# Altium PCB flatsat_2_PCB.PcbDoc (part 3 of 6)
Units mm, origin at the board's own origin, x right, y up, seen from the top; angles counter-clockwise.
Board outline 400 x 250 mm, 4 copper layers (Top Layer, FlatSat GND, FlatSat VCC, Bottom Layer), stack 2.102 mm thick; 196 components, 289 nets, 1724 pads, 1139 vias.
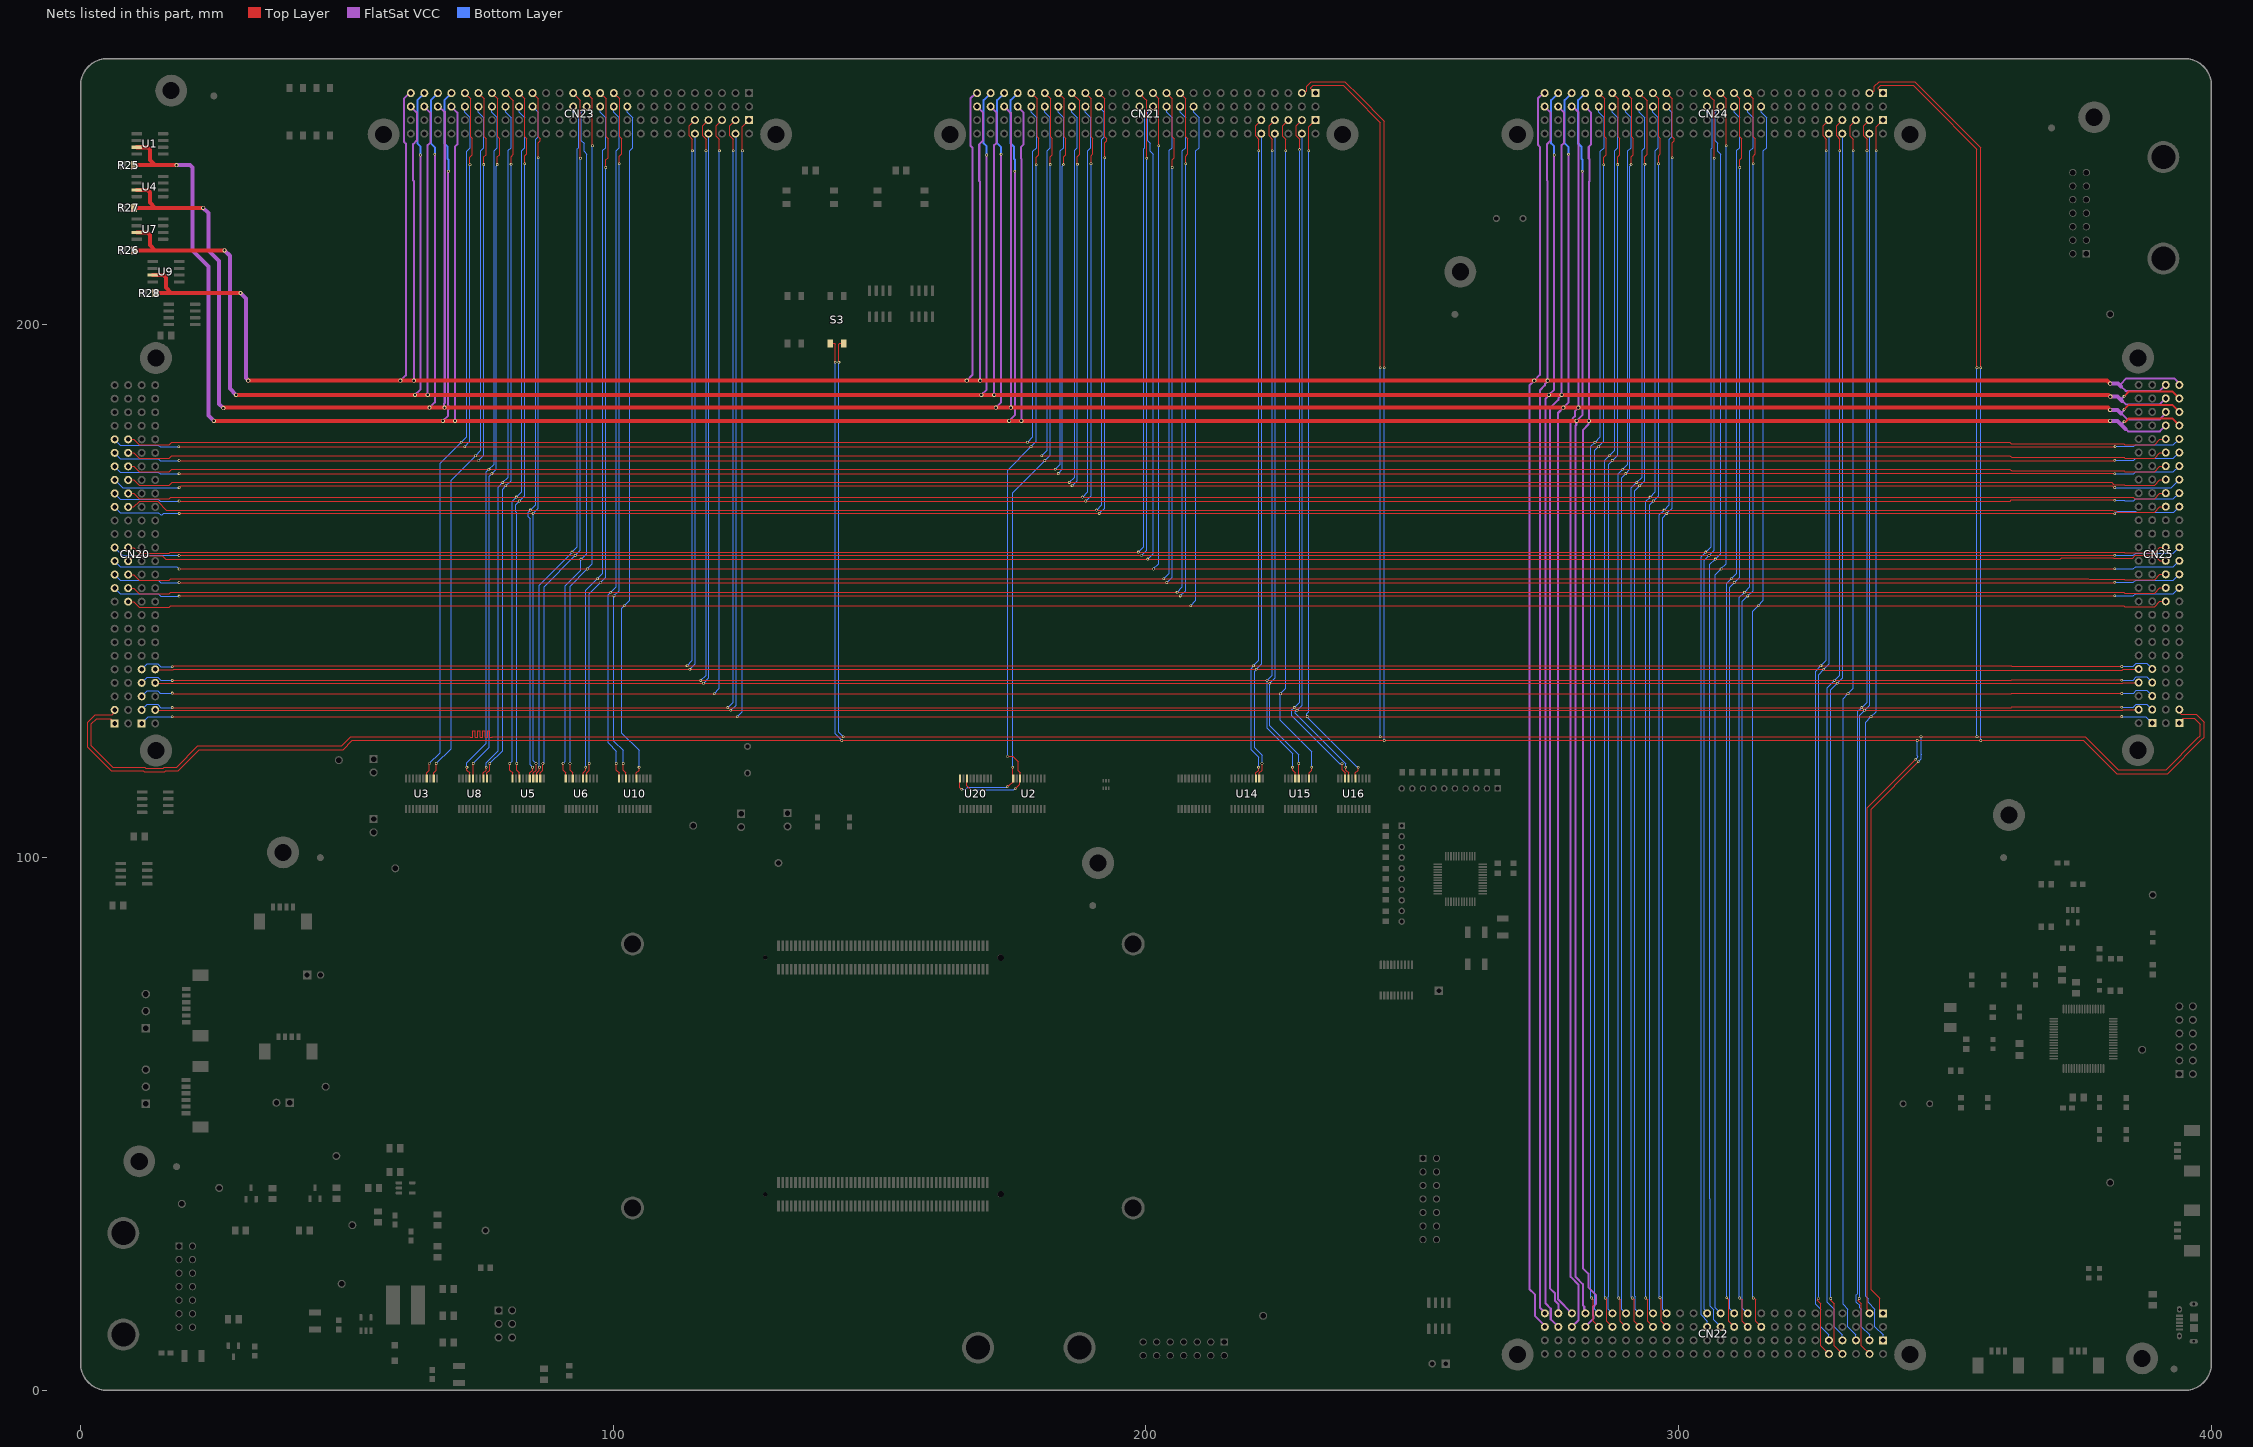
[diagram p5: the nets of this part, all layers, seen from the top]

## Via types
v1: diameter 0.508, hole 0.3, Top Layer to Bottom Layer, tented both sides, 1073 vias
v2: diameter 0.762, hole 0.45, Top Layer to Bottom Layer, tented both sides, 66 vias

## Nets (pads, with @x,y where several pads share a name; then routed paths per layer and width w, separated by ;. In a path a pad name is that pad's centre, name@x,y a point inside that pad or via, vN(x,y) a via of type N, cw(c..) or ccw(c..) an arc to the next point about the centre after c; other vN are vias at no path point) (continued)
H1-20: CN20.20 CN21.20 CN22.20 CN23.20 CN24.20 CN25.20 U10.15 | length 838.6
  Top Layer w0.203: CN20.20@8.92,148.06 10.004,148.06 11.034,147.03 16.604,147.03 16.88,147.307 v1(102.058,147.307) v1(208.378,147.307) v1(314.918,147.307) 383.54,147.307 383.762,147.085 389.332,147.085 390.361,148.115 CN25.20@391.445,148.115 ; U10.15@104.325,114.87 104.325,115.913 104.832,116.421 v1(104.832,116.994) ; v1(313.991,17.333) 314.145,17.333 314.479,16.999 314.479,13.945 314.48,13.944 314.48,13 315.508,11.972 CN22.20@315.508,11.923
  Bottom Layer w0.203: CN23.20@102.62,241 102.62,239.916 103.65,238.886 103.65,233.316 103.058,232.725 103.058,148.307 v1(102.058,147.307) 101.597,146.847 101.597,123.403 104.832,120.168 v1(104.832,116.994) ; v1(208.378,147.307) 209.378,148.307 209.378,232.725 209.97,233.316 209.97,238.886 208.94,239.916 CN21.20@208.94,241 ; v1(313.991,17.333) 313.932,17.391 313.932,17.59 313.918,17.605 313.918,36 313.918,146.307 v1(314.918,147.307) 315.918,148.307 315.918,232.725 316.51,233.316 316.51,238.886 315.48,239.916 CN24.20@315.48,241
H1-21: CN20.21 CN21.21 CN22.21 CN23.21 CN24.21 CN25.21 U10.18 | length 846.4
  Top Layer w0.203: v1(18.478,149.113) 18.505,149.14 v1(100.119,149.14) v1(206.439,149.14) v1(312.979,149.14) 381.861,149.14 v1(381.887,149.166) ; CN23.21@100.08,243.54 101.17,242.45 101.17,235.319 101.562,234.928 101.562,232.163 101.119,231.72 v1(101.119,230.295) ; v1(101.868,117.679) 101.868,116.421 102.375,115.913 U10.18@102.375,114.87 ; CN21.21@206.4,243.54 207.49,242.45 207.49,235.319 207.882,234.928 207.882,232.163 207.439,231.72 v1(207.439,230.295) ; CN24.21@312.94,243.54 314.03,242.45 314.03,235.319 314.422,234.928 314.422,232.163 313.979,231.72 v1(313.979,230.295)
  Bottom Layer w0.203: CN20.21@6.38,150.6 7.47,149.51 14.601,149.51 14.992,149.118 18.473,149.118 v1(18.478,149.113) ; v1(101.119,230.295) 101.119,150.14 v1(100.119,149.14) 100.119,121.881 101.868,120.132 v1(101.868,117.679) ; v1(206.439,149.14) 207.439,150.14 v1(207.439,230.295) ; CN22.21@312.968,14.463 311.979,15.452 311.979,36 311.979,148.14 v1(312.979,149.14) 313.979,150.14 v1(313.979,230.295) ; v1(381.887,149.166) 385.365,149.166 385.765,149.565 392.895,149.565 CN25.21@393.985,150.655
H1-22: CN20.22 CN21.22 CN22.22 CN23.22 CN24.22 CN25.22 U10.20 | length 835.4
  Top Layer w0.203: CN20.22@8.92,150.6 10.004,150.6 11.034,149.57 16.604,149.57 16.88,149.847 v1(99.517,149.847) v1(205.837,149.847) v1(312.377,149.847) 383.54,149.847 383.762,149.625 389.332,149.625 390.361,150.655 CN25.22@391.445,150.655 ; v1(100.568,117.679) 100.568,116.421 101.075,115.913 U10.20@101.075,114.87 ; v1(311.446,17.333) 311.605,17.333 311.939,16.999 311.939,13.945 311.94,13.944 311.94,13 312.968,11.972 CN22.22@312.968,11.923
  Bottom Layer w0.203: CN23.22@100.08,241 100.08,239.916 101.11,238.886 101.11,233.316 100.517,232.724 100.517,150.847 v1(99.517,149.847) 99,149.33 99,121.529 100.568,119.962 v1(100.568,117.679) ; v1(205.837,149.847) 206.837,150.847 206.837,232.724 207.43,233.316 207.43,238.886 206.4,239.916 CN21.22@206.4,241 ; v1(311.446,17.333) 311.387,17.391 311.387,17.594 311.377,17.605 311.377,36 311.377,148.847 v1(312.377,149.847) 313.377,150.847 313.377,232.724 313.97,233.316 313.97,238.886 312.94,239.916 CN24.22@312.94,241
H1-23: CN20.23 CN21.23 CN22.23 CN23.23 CN24.23 CN25.23 U6.14 | length 843.9
  Top Layer w0.203: v1(18.478,151.653) v1(97.584,151.653) v1(203.904,151.653) v1(310.444,151.653) 381.832,151.653 v1(381.887,151.708) ; U6.14@94.975,114.87 94.975,115.913 95.482,116.421 v1(95.482,117.679) ; CN23.23@97.54,243.54 98.63,242.45 98.63,235.319 99.027,234.923 99.027,231.442 98.584,230.999 v1(98.584,229.574) ; CN21.23@203.86,243.54 204.95,242.45 204.95,235.319 205.347,234.923 205.347,231.442 204.904,230.999 v1(204.904,229.574) ; CN24.23@310.4,243.54 311.49,242.45 311.49,235.319 311.887,234.923 311.887,231.442 311.444,230.999 v1(311.444,229.574)
  Bottom Layer w0.203: CN20.23@6.38,153.14 7.47,152.05 14.601,152.05 14.997,151.653 v1(18.478,151.653) ; v1(95.482,117.679) 95.482,149.552 v1(97.584,151.653) 98.584,152.653 v1(98.584,229.574) ; v1(203.904,151.653) 204.904,152.653 v1(204.904,229.574) ; CN22.23@310.428,14.463 309.575,15.317 309.575,150.784 v1(310.444,151.653) 311.444,152.653 v1(311.444,229.574) ; v1(381.887,151.708) 385.368,151.708 385.765,152.105 392.895,152.105 CN25.23@393.985,153.195
H1-24: CN20.24 CN21.24 CN22.24 CN23.24 CN24.24 CN25.24 U6.15 | length 832.6
  Top Layer w0.203: CN20.24@8.92,153.14 10.004,153.14 11.034,152.11 16.604,152.11 16.88,152.387 v1(97.018,152.387) v1(203.338,152.387) v1(309.878,152.387) 377,152.387 377.145,152.242 383.685,152.242 383.762,152.165 389.332,152.165 390.361,153.195 CN25.24@391.445,153.195 ; U6.15@94.325,114.87 94.325,115.913 94.832,116.421 v1(94.832,116.994) ; v1(309.041,17.37) 309.041,17.357 309.399,16.999 309.399,13.945 309.4,13.944 309.4,13 310.428,11.972 CN22.24@310.428,11.923
  Bottom Layer w0.203: v1(94.832,116.994) 94.832,150.201 v1(97.018,152.387) 98.018,153.387 98.018,232.765 98.57,233.316 98.57,238.886 97.54,239.916 CN23.24@97.54,241 ; v1(203.338,152.387) 204.338,153.387 204.338,232.765 204.89,233.316 204.89,238.886 203.86,239.916 CN21.24@203.86,241 ; v1(309.041,17.37) 309.041,151.55 310.878,153.387 310.878,232.765 311.43,233.316 311.43,238.886 310.4,239.916 CN24.24@310.4,241
H1-25: CN20.25 CN21.25 CN22.25 CN23.25 CN24.25 CN25.25 U6.18 | length 841
  Top Layer w0.203: v1(18.478,154.193) v1(95.086,154.193) v1(201.406,154.193) 307.946,154.193 381.832,154.193 v1(381.887,154.248) ; v1(91.868,117.679) 91.868,116.421 92.375,115.913 U6.18@92.375,114.87 ; CN23.25@95,243.54 96.086,242.454 v1(96.086,233.675) ; CN21.25@201.32,243.54 202.406,242.454 v1(202.406,233.675) ; CN24.25@307.86,243.54 308.946,242.454 v1(308.946,233.675) ; v1(307.96,154.184) v1@307.96,154.193
  Bottom Layer w0.203: CN20.25@6.38,155.68 7.466,154.594 18.078,154.594 v1(18.478,154.193) ; v1(91.868,117.679) 91.868,150.975 v1(95.086,154.193) 96.086,155.193 v1(96.086,233.675) ; v1(201.406,154.193) 202.406,155.193 v1(202.406,233.675) ; CN22.25@307.888,14.463 306.855,15.496 306.855,153.103 307.864,154.112 307.888,154.112 v1(307.96,154.184) ; v1@307.946,154.193 308.946,155.193 v1(308.946,233.675) ; v1(381.887,154.248) 385.368,154.248 385.765,154.645 392.895,154.645 CN25.25@393.985,155.735
H1-26: CN20.26 CN21.26 CN22.26 CN23.26 CN24.26 CN25.26 U6.20 | length 830.8
  Top Layer w0.203: CN20.26@8.92,155.68 9.95,156.71 15.29,156.71 15.94,156.06 94.007,156.06 200.336,156.06 v1(306.876,156.06) 371.626,156.06 371.884,156.318 381.602,156.318 381.666,156.255 385.244,156.255 385.754,156.764 389.332,156.764 390.361,155.735 CN25.26@391.445,155.735 ; v1(90.568,117.679) 90.568,116.421 91.075,115.913 U6.20@91.075,114.87
  Bottom Layer w0.203: v1(90.568,117.679) 91,118.111 91,151.039 92.183,152.222 93.922,153.961 v1(93.922,156.06) ; v1@94.007,156.06 94.016,156.06 95.016,157.06 95.016,232.075 94.504,232.587 94.504,234.096 93.97,234.63 93.97,239.97 CN23.26@95,241 ; v1(200.327,156.06) 200.336,156.06 201.336,157.06 201.336,232.075 200.824,232.587 200.824,234.096 200.29,234.63 200.29,239.97 CN21.26@201.32,241 ; CN24.26@307.86,241 306.83,239.97 306.83,234.63 307.364,234.096 307.364,232.587 307.876,232.075 307.876,157.06 v1(306.876,156.06) 305.876,155.06 305.876,36 305.888,35.987 305.888,15.799 306.571,15.117 306.571,13.241 CN22.26@307.888,11.923
H1-27: CN20.27 CN21.27 CN22.27 CN23.27 CN24.27 CN25.27 U5.12 | length 839.7
  Top Layer w0.203: v1(18.478,156.733) v1(92.836,156.733) v1(199.156,156.733) v1(305.696,156.733) 381.832,156.733 v1(381.887,156.788) ; U5.12@86.275,114.87 86.275,115.913 86.782,116.421 v1(86.782,117.679) ; CN23.27@92.46,243.54 93.49,242.51 93.836,242.164 v1(93.836,231.331) ; CN21.27@198.78,243.54 199.81,242.51 200.156,242.164 v1(200.156,231.331) ; CN24.27@305.32,243.54 306.35,242.51 306.696,242.164 v1(306.696,231.331)
  Bottom Layer w0.203: CN20.27@6.38,158.22 7.41,157.19 7.867,156.733 v1(18.478,156.733) ; v1(86.782,117.679) 86.782,117.733 87,117.95 87,150.898 v1(92.836,156.733) 93.836,157.733 v1(93.836,231.331) ; v1(199.156,156.733) 200.156,157.733 v1(200.156,231.331) ; CN22.27@305.348,14.463 305.348,14.709 304.821,15.236 304.821,35.995 304.826,36 304.826,155.864 v1(305.696,156.733) 306.696,157.733 v1(306.696,231.331) ; v1(381.887,156.788) 385.368,156.788 385.765,157.185 392.895,157.185 CN25.27@393.985,158.275
H1-28: CN20.28 CN21.28 CN22.28 CN23.28 CN24.28 CN25.28 U5.13 | length 828.8
  Top Layer w0.203: CN20.28@8.92,158.22 10.004,158.22 11.034,157.19 16.604,157.19 16.78,157.367 v1(92.235,157.367) v1(198.555,157.367) v1(305.095,157.367) 383.64,157.367 383.762,157.245 389.332,157.245 390.361,158.275 CN25.28@391.445,158.275 ; U5.13@85.625,114.87 85.625,115.913 86.132,116.421 v1(86.132,116.994)
  Bottom Layer w0.203: v1(86.132,116.994) 86.132,151.132 92.109,157.109 92.109,157.158 92.235,157.284 v1(92.235,157.367) 93.235,158.367 93.235,233.062 93.49,233.316 93.49,238.886 92.46,239.916 CN23.28@92.46,241 ; v1(198.555,157.367) 199.555,158.367 199.555,233.062 199.81,233.316 199.81,238.886 198.78,239.916 CN21.28@198.78,241 ; CN24.28@305.32,241 305.32,239.916 306.35,238.886 306.35,233.316 306.095,233.062 306.095,158.367 v1(305.095,157.367) 304.21,156.481 304.21,36 304.21,14.146 305.348,13.007 CN22.28@305.348,11.923
H1-33: CN20.33 CN21.33 CN22.33 CN23.33 CN24.33 CN25.33 U5.14 | length 830.4
  Top Layer w0.203: v1(18.5,164.623) v1(84.93,164.623) v1(191.25,164.623) v1(297.79,164.623) 381.779,164.623 v1(381.851,164.551) ; CN23.33@84.84,243.54 85.93,242.45 85.93,235.319 86.327,234.923 86.327,234.57 85.93,234.173 v1(85.93,231.42) ; U5.14@84.975,114.87 84.975,115.913 85.482,116.421 v1(85.482,117.679) ; CN21.33@191.16,243.54 192.25,242.45 192.25,235.319 192.647,234.923 192.647,234.57 192.25,234.173 v1(192.25,231.42) ; CN24.33@297.7,243.54 298.79,242.45 298.79,235.319 299.187,234.923 299.187,234.57 298.79,234.173 v1(298.79,231.42)
  Bottom Layer w0.203: CN20.33@6.38,165.84 7.47,164.75 14.601,164.75 14.997,164.353 15.35,164.353 15.619,164.623 v1(18.5,164.623) ; v1(85.482,117.679) 84.92,118.241 84.92,164.613 v1(84.93,164.623) 85.93,165.622 v1(85.93,231.42) ; v1(191.25,164.623) 192.25,165.622 v1(192.25,231.42) ; CN22.33@297.728,14.463 297.728,14.55 297.026,15.252 297.026,163.859 v1(297.79,164.623) 298.789,165.622 v1(298.79,231.42) ; v1(381.851,164.551) 382.339,165.04 385.764,165.04 385.939,164.865 392.956,164.865 CN25.33@393.985,165.895
H1-34: CN20.34 CN21.34 CN22.34 CN23.34 CN24.34 CN25.34 U5.15 | length 820
  Top Layer w0.203: CN20.34@8.92,165.84 10.004,165.84 11.054,166.89 14.435,166.89 16.068,165.257 v1(84.396,165.257) v1(190.716,165.257) v1(297.256,165.257) 381.532,165.257 381.704,165.085 382.072,165.085 382.291,164.865 389.332,164.865 390.361,165.895 CN25.34@391.445,165.895 ; U5.15@84.325,114.87 84.325,115.913 84.832,116.421 v1(84.832,116.994) ; v1(296.492,17.356) 296.492,17.206 296.699,16.999 296.699,13.945 296.7,13.944 296.7,13 297.728,11.972 CN22.34@297.728,11.923
  Bottom Layer w0.203: v1(84.832,116.994) 84.387,117.44 84.387,163.613 84,164 84,164.861 v1(84.396,165.257) 85.396,166.257 85.396,234.913 85.87,235.386 85.87,239.97 CN23.34@84.84,241 ; v1(190.716,165.257) 191.716,166.257 191.716,234.903 192.19,235.377 192.19,239.97 CN21.34@191.16,241 ; v1(296.492,17.356) 296.464,17.356 296.345,17.475 296.345,36 296.345,164.346 v1(297.256,165.257) 298.256,166.257 298.256,234.887 298.73,235.361 298.73,239.97 CN24.34@297.7,241
H1-35: CN20.35 CN21.35 CN22.35 CN23.35 CN24.35 CN25.35 U5.18 | length 827.9
  Top Layer w0.203: v1(18.478,166.954) v1(82.36,166.954) v1(188.68,166.954) v1(295.22,166.954) 362.236,166.954 362.434,167.152 381.839,167.152 v1(381.887,167.104) ; v1(81.868,117.679) 81.868,116.421 82.375,115.913 U5.18@82.375,114.87 ; CN23.35@82.3,243.54 83.39,242.45 83.39,235.319 83.726,234.983 83.726,232.157 83.36,231.79 v1(83.36,230.277) ; CN21.35@188.62,243.54 189.71,242.45 189.71,235.319 190.046,234.983 190.046,232.157 189.68,231.79 v1(189.68,230.277) ; CN24.35@295.16,243.54 296.25,242.45 296.25,235.319 296.586,234.983 296.586,232.157 296.22,231.79 v1(296.22,230.277)
  Bottom Layer w0.203: CN20.35@6.38,168.38 7.47,167.29 14.601,167.29 14.937,166.954 v1(18.478,166.954) ; v1(81.868,117.679) 81.868,164.694 81.646,164.915 81.646,166.24 v1(82.36,166.954) 83.36,167.954 v1(83.36,230.277) ; v1(188.68,166.954) 189.68,167.954 v1(189.68,230.277) ; CN22.35@295.188,14.463 295.188,14.468 294.529,15.127 294.529,166.263 v1(295.22,166.954) 296.22,167.954 v1(296.22,230.277) ; v1(381.887,167.104) 383.651,167.104 383.746,167.009 385.428,167.009 385.765,167.345 392.895,167.345 CN25.35@393.985,168.435
H1-36: CN20.36 CN21.36 CN22.36 CN23.36 CN24.36 CN25.36 U5.20 | length 817
  Top Layer w0.203: CN20.36@8.92,168.38 10.004,168.38 11.034,167.35 16.604,167.35 16.95,167.697 v1(81.768,167.697) v1(188.088,167.697) v1(294.628,167.697) 385.294,167.697 385.586,167.405 389.332,167.405 390.361,168.435 CN25.36@391.445,168.435 ; v1(80.568,117.679) 80.568,116.421 81.075,115.913 U5.20@81.075,114.87 ; v1(293.825,17.333) 294.159,16.999 294.159,13.945 294.16,13.944 294.16,13 295.188,11.972 CN22.36@295.188,11.923
  Bottom Layer w0.203: v1(80.568,117.679) 81,118.111 81,166.929 v1(81.768,167.697) 82.768,168.697 82.768,232.755 83.33,233.316 83.33,238.886 82.3,239.916 CN23.36@82.3,241 ; v1(188.088,167.697) 189.088,168.697 189.088,232.755 189.65,233.316 189.65,238.886 188.62,239.916 CN21.36@188.62,241 ; v1(293.825,17.333) 293.811,17.347 293.811,36 293.811,166.88 v1(294.628,167.697) 295.628,168.697 295.628,232.755 296.19,233.316 296.19,238.886 295.16,239.916 CN24.36@295.16,241
H1-37: CN20.37 CN21.37 CN22.37 CN23.37 CN24.37 CN25.37 U8.12 | length 826.5
  Top Layer w0.203: v1(18.478,169.433) 18.85,169.805 v1(79.804,169.805) v1(186.124,169.805) v1(292.664,169.805) 381.382,169.805 381.699,169.488 v1(381.887,169.488) v1@381.832,169.433 ; U8.12@76.275,114.87 76.275,115.913 76.782,116.421 v1(76.782,117.679) ; CN23.37@79.76,243.54 81.247,242.053 81.247,232.063 80.804,231.621 v1(80.804,230.196) ; CN21.37@186.08,243.54 187.567,242.053 187.567,232.063 187.124,231.621 v1(187.124,230.196) ; CN24.37@292.62,243.54 294.107,242.053 294.107,232.063 293.664,231.621 v1(293.664,230.196)
  Bottom Layer w0.203: CN20.37@6.38,170.92 7.867,169.433 v1(18.478,169.433) ; v1(76.782,117.679) 79.207,120.103 79.207,169.208 v1(79.804,169.805) 80.804,170.805 v1(80.804,230.196) ; v1(186.124,169.805) 187.124,170.805 v1(187.124,230.196) ; CN22.37@292.648,14.463 291.865,15.247 291.865,17.557 291.775,17.647 291.775,36 291.775,168.916 v1(292.664,169.805) 293.664,170.805 v1(293.664,230.196) ; v1(381.887,169.488) 392.499,169.488 CN25.37@393.985,170.975
H1-38: CN20.38 CN21.38 CN22.38 CN23.38 CN24.38 CN25.38 U8.13 | length 815.3
  Top Layer w0.203: CN20.38@8.92,170.92 10.004,170.92 11.034,169.89 16.604,169.89 17.156,170.443 v1(79.258,170.443) v1(185.578,170.443) v1(292.118,170.443) 381.283,170.443 381.704,170.022 383.685,170.022 383.762,169.945 389.332,169.945 390.361,170.975 CN25.38@391.445,170.975 ; U8.13@75.625,114.87 75.625,115.913 76.132,116.421 v1(76.132,116.994) ; v1(291.285,17.333) 291.619,16.999 291.619,13.945 291.62,13.944 291.62,13 292.648,11.972 CN22.38@292.648,11.923
  Bottom Layer w0.203: v1(76.132,116.994) 76.132,117.783 78.381,120.032 78.381,169.567 v1(79.258,170.443) 80.258,171.443 80.258,232.785 80.79,233.316 80.79,238.886 79.76,239.916 CN23.38@79.76,241 ; v1(185.578,170.443) 186.578,171.443 186.578,232.785 187.11,233.316 187.11,238.886 186.08,239.916 CN21.38@186.08,241 ; v1(291.285,17.333) 291.118,17.5 291.118,36 291.118,169.443 v1(292.118,170.443) 293.118,171.443 293.118,232.785 293.65,233.316 293.65,238.886 292.62,239.916 CN24.38@292.62,241
H1-39: CN20.39 CN21.39 CN22.39 CN23.39 CN24.39 CN25.39 U8.16 | length 823.4
  Top Layer w0.203: v1(18.472,172.081) 18.478,172.087 18.727,172.087 18.744,172.103 v1(77.209,172.103) v1(183.529,172.103) v1(290.069,172.103) 290.128,172.162 290.295,172.162 290.341,172.207 381.687,172.207 381.811,172.083 v1(381.893,172.083) ; U8.16@73.675,114.87 v1(73.675,117.679) ; CN23.39@77.22,243.54 78.31,242.45 78.31,235.319 78.652,234.978 78.652,231.983 78.209,231.54 v1(78.209,230.115) ; CN21.39@183.54,243.54 184.63,242.45 184.63,235.319 184.972,234.978 184.972,231.983 184.529,231.54 v1(184.529,230.115) ; CN24.39@290.08,243.54 291.17,242.45 291.17,235.319 291.512,234.978 291.512,231.983 291.069,231.54 v1(291.069,230.115)
  Bottom Layer w0.203: CN20.39@6.38,173.46 7.47,172.37 14.601,172.37 14.901,172.069 18.461,172.069 v1(18.472,172.081) ; v1(73.675,117.679) 76.722,120.726 76.722,171.616 v1(77.209,172.103) 78,172.894 78,229.844 78.209,230.053 v1(78.209,230.115) ; v1(183.529,172.103) 184.32,172.894 184.32,229.844 184.529,230.053 v1(184.529,230.115) ; 289.86,171.894 289.328,171.362 289.328,36 289.328,17.568 289.321,17.56 289.325,17.557 289.325,15.247 CN22.39@290.108,14.463 ; v1(290.069,172.103) 290.86,172.894 290.86,229.844 291.069,230.053 v1(291.069,230.115) ; v1(381.893,172.083) 385.423,172.083 385.765,172.425 392.895,172.425 CN25.39@393.985,173.515
H1-40: CN20.40 CN21.40 CN22.40 CN23.40 CN24.40 CN25.40 U8.17 | length 813.2
  Top Layer w0.203: CN20.40@8.92,173.46 10.004,173.46 11.034,172.43 16.604,172.43 17.093,172.92 v1(76.644,172.92) v1(182.964,172.92) v1(289.504,172.92) 362.182,172.92 362.486,172.617 383.63,172.617 383.762,172.485 389.332,172.485 390.361,173.515 CN25.40@391.445,173.515 ; v1(72.518,116.994) 72.518,116.421 73.025,115.913 U8.17@73.025,114.87 ; v1(288.745,17.333) 289.079,16.999 289.079,13.945 289.08,13.944 289.08,13 290.108,11.972 CN22.40@290.108,11.923
  Bottom Layer w0.203: v1(72.518,116.994) 72.518,117.79 76.173,121.446 76.173,172.45 v1(76.644,172.92) 77.601,173.878 77.601,232.668 78.25,233.316 78.25,238.886 77.22,239.916 CN23.40@77.22,241 ; v1(182.964,172.92) 183.921,173.878 183.921,232.668 184.57,233.316 184.57,238.886 183.54,239.916 CN21.40@183.54,241 ; v1(288.745,17.333) 288.687,17.391 288.687,17.556 288.638,17.605 288.638,35.999 288.637,36 288.637,172.054 v1@289.461,172.878 ; v1(289.504,172.92) 290.461,173.878 290.461,232.668 291.11,233.316 291.11,238.886 290.08,239.916 CN24.40@290.08,241
H1-41: CN20.41 CN21.41 CN22.41 CN23.41 CN24.41 CN25.41 U2.20 U20.20 | length 835.4
  Top Layer w0.203: v1(18.475,174.556) v1(74.682,174.556) v1(181.002,174.556) v1(287.542,174.556) 381.836,174.556 v1(381.891,174.611) ; CN23.41@74.68,243.54 75.77,242.45 75.77,235.319 76.124,234.965 76.124,231.982 75.682,231.54 v1(75.682,230.115) ; U20.20@165.075,114.87 165.075,113.168 v1(165.39,112.853) ; v1(173.933,113.302) 173.933,113.384 174.127,113.579 ; 174.127,113.58 174.365,113.58 175.075,114.29 U2.20@175.075,114.87 175,114.945 v1(175,117) ; CN21.41@181,243.54 182.09,242.45 182.09,235.319 182.444,234.965 182.444,231.982 182.002,231.54 v1(182.002,230.115) ; CN24.41@287.54,243.54 288.63,242.45 288.63,235.319 288.984,234.965 288.984,231.982 288.542,231.54 v1(288.542,230.115)
  Bottom Layer w0.203: CN20.41@6.38,176 7.47,174.91 14.601,174.91 14.955,174.556 v1(18.475,174.556) ; v1(74.682,174.556) 75.682,175.556 v1(75.682,230.115) ; v1(165.39,112.853) 166.163,112.853 166.564,113.254 173.885,113.254 v1(173.933,113.302) ; v1(175,117) 175,168.554 v1(181.002,174.556) 182.002,175.556 v1(182.002,230.115) ; CN22.41@287.568,14.463 286.785,15.247 286.785,17.557 286.781,17.56 286.838,17.618 286.838,36 286.838,173.852 v1(287.542,174.556) 288.542,175.556 v1(288.542,230.115) ; v1(381.891,174.611) 385.41,174.611 385.765,174.965 392.895,174.965 CN25.41@393.985,176.055
H1-42: CN20.42 CN21.42 CN22.42 CN23.42 CN24.42 CN25.42 U3.12 | length 812
  Top Layer w0.203: CN20.42@8.92,176 10.004,176 11.034,174.97 16.604,174.97 17.093,175.46 v1(74.132,175.46) v1(180.452,175.46) v1(286.992,175.46) 362.182,175.46 362.498,175.144 383.643,175.144 383.762,175.025 389.332,175.025 390.361,176.055 CN25.42@391.445,176.055 ; U3.12@66.275,114.87 66.275,115.913 66.782,116.421 v1(66.782,117.679) ; v1(286.205,17.333) 286.539,16.999 286.539,13.945 286.54,13.944 286.54,13 287.568,11.972 CN22.42@287.568,11.923
  Bottom Layer w0.203: v1(66.782,117.679) 69.568,120.464 69.568,170.896 v1(74.132,175.46) 75.132,176.46 75.132,232.739 75.71,233.316 75.71,238.886 74.68,239.916 CN23.42@74.68,241 ; v1(180.452,175.46) 181.452,176.46 181.452,232.739 182.03,233.316 182.03,238.886 181,239.916 CN21.42@181,241 ; v1(286.205,17.333) 286.147,17.391 286.147,17.569 286.111,17.605 286.111,36 286.111,174.579 v1(286.992,175.46) 287.992,176.46 287.992,232.739 288.57,233.316 288.57,238.886 287.54,239.916 CN24.42@287.54,241
H1-43: CN20.43 CN21.43 CN22.43 CN23.43 CN24.43 CN25.43 U2.18 U20.18 | length 833.9
  Top Layer w0.203: v1(18.44,177.149) v1(72.088,177.149) v1(178.408,177.149) v1(284.948,177.149) 381.87,177.149 v1(381.925,177.204) ; CN23.43@72.14,243.54 73.23,242.45 73.23,235.319 73.531,235.019 73.531,231.927 73.088,231.485 v1(73.088,230.06) ; U20.18@166.375,114.87 166.375,113.457 167.158,112.673 v1(167.158,112.608) ; v1(174,119) 175,119 176,118 176,116.288 176.375,115.913 U2.18@176.375,114.87 176.272,114.767 176.272,113.798 v1(175.426,112.952) ; CN21.43@178.46,243.54 179.55,242.45 179.55,235.319 179.851,235.019 179.851,231.927 179.408,231.485 v1(179.408,230.06) ; CN24.43@285,243.54 286.09,242.45 286.09,235.319 286.391,235.019 286.391,231.927 285.948,231.485 v1(285.948,230.06)
  Bottom Layer w0.203: CN20.43@6.38,178.54 7.47,177.45 14.601,177.45 14.901,177.149 v1(18.44,177.149) ; v1(72.088,177.149) 73.088,178.149 v1(73.088,230.06) ; v1(167.158,112.608) 167.238,112.688 167.717,112.688 167.902,112.873 168.364,112.873 168.487,112.75 175.155,112.75 175.357,112.952 v1(175.426,112.952) ; v1(174,119) 174,172.741 v1(178.408,177.149) 179.408,178.149 v1(179.408,230.06) ; CN22.43@285.028,14.463 284.245,15.247 284.245,36 284.245,176.446 v1(284.948,177.149) 285.948,178.149 v1(285.948,230.06) ; v1(381.925,177.204) 385.464,177.204 385.765,177.505 392.895,177.505 CN25.43@393.985,178.595
H1-44: CN20.44 CN21.44 CN22.44 CN23.44 CN24.44 CN25.44 U3.14 | length 809
  Top Layer w0.203: CN20.44@8.92,178.54 10.004,178.54 11.034,177.51 16.604,177.51 17.093,178 v1(71.437,178) v1(177.757,178) v1(284.297,178) 362.182,178 362.445,177.738 383.589,177.738 383.762,177.565 389.332,177.565 390.361,178.595 CN25.44@391.445,178.595 ; U3.14@64.975,114.87 64.975,115.913 65.482,116.421 v1(65.482,117.679) ; v1(283.665,17.333) 283.999,16.999 283.999,13.945 284,13.944 284,13 285.028,11.972 CN22.44@285.028,11.923
  Bottom Layer w0.203: v1(65.482,117.679) 67.483,119.68 67.483,174.047 v1(71.437,178) 72.437,179 72.437,232.583 73.17,233.316 73.17,238.886 72.14,239.916 CN23.44@72.14,241 ; v1(177.757,178) 178.757,179 178.757,232.583 179.49,233.316 179.49,238.886 178.46,239.916 CN21.44@178.46,241 ; v1(283.665,17.333) 283.494,17.504 283.494,36 283.494,177.197 v1(284.297,178) 285.297,179 285.297,232.583 286.03,233.316 286.03,238.886 285,239.916 CN24.44@285,241
H1-45: CN21.45 CN21.46 CN22.45 CN22.46 CN23.45 CN23.46 CN24.45 CN24.46 CN25.45 CN25.46 R25.2 U1.7 | length 1154.7
  Top Layer w0.381: v1(383.623,181.835) 383.915,181.835 384.54,182.46 392.66,182.46 CN25.45@393.985,181.135
  Top Layer w0.762: R25.2@10.016,230 14,230 ; U1.7@10.53,233.365 12.554,233.365 13,232.919 13,231 14,230 ; v2(18,230) 14,230 ; v2(25,182) v2(67.985,182) v2(70.28,182) v2(174.305,182) v2(176.6,182) v2(280.845,182) v2(283.14,182) v2(381,182)
  FlatSat VCC w0.381: v2(67.985,182) 68.985,183 68.985,184.102 69.058,184.175 69.058,184.796 68.985,184.869 68.985,228.759 69.058,228.832 v1(69.058,228.866) ; CN23.46@69.6,241 70.719,239.881 70.719,237.223 70.719,233.922 70.318,233.521 70.318,228.625 70.318,182 v2(70.28,182) ; v2(174.305,182) 175.378,183.073 v1(175.378,228.866) ; CN21.46@175.92,241 177.039,239.881 177.039,237.223 177.039,233.922 176.577,233.46 176.577,231.243 176.67,231.15 176.67,182.07 v2(176.6,182) ; v1(281.918,228.866) 281.918,183.073 v2(280.845,182) 280.772,181.927 280.772,181.262 280.63,181.12 280.63,21.319 282,19.949 282,16 282.274,15.726 282.274,14.677 CN22.45@282.488,14.463 ; CN24.46@282.46,241 283.579,239.881 283.579,237.223 283.579,233.922 283.117,233.46 283.117,231.243 283.265,231.095 283.265,227 283.14,226.875 v2(283.14,182) 283.067,181.927 283.067,181.343 282,180.276 282,22.928 283.034,21.893 283.034,19.333 284.495,17.873 284.495,16.23 283.91,15.644 283.91,14 284,13.91 284,13.472 282.488,11.96 CN22.46@282.488,11.923 ; 383.144,181.239 383.144,181.322 383.623,181.801 v1(383.623,181.835) ; 383.905,180.478 384.367,180.016 387.668,180.016 390.327,180.016 CN25.46@391.445,181.135
  FlatSat VCC w0.762: v2(18,230) 20.554,230 21,229.554 21,214 24,211 24,183 v2(25,182) ; v2(381,182) 382.383,182 383.144,181.239 383.905,180.478
  Bottom Layer w0.381: v1(69.058,228.866) 69.058,231.026 68.9,231.184 68.9,233.47 68.275,234.095 68.275,242.215 CN23.45@69.6,243.54 ; v1(175.378,228.866) 175.378,231.026 175.22,231.184 175.22,233.47 174.595,234.095 174.595,242.215 CN21.45@175.92,243.54 ; v1(281.918,228.866) 281.918,231.026 281.76,231.184 281.76,233.47 281.135,234.095 281.135,242.215 CN24.45@282.46,243.54
H1-47: CN21.47 CN21.48 CN22.47 CN22.48 CN23.47 CN23.48 CN24.47 CN24.48 CN25.47 CN25.48 R27.2 U4.7 | length 1134.3
  Top Layer w0.381: v1(383.623,184.154) 384.469,185 392.66,185 CN25.47@393.985,183.675
  Top Layer w0.762: R27.2@10.016,222 14,222 ; U4.7@10.53,225.365 12.554,225.365 13,224.919 13,223 14,222 ; v2(23,222) 14,222 ; v2(26.775,184.402) 26.859,184.486 v2(65.495,184.486) v2(68.309,184.486) v2(174.629,184.486) v2(281.169,184.486) 380.585,184.486 v2(381,184.071)
  FlatSat VCC w0.381: v2(65.495,184.486) 66.495,185.486 66.495,232.015 v1(66.477,232.033) ; CN23.48@67.32,241 68.354,239.966 68.354,185.354 68.241,185.241 68.241,184.687 68.174,184.62 v2(68.309,184.486) ; v2(171.815,184.486) 172.815,185.486 172.815,232.015 v1(172.797,232.033) ; CN21.48@173.64,241 173.64,240.74 174.629,239.751 v2(174.629,184.486) ; v1(279.337,232.033) 279.355,232.015 279.355,185.486 v2(278.355,184.486) 277.344,183.475 277.344,17.067 CN22.47@279.948,14.463 ; CN22.48@279.948,11.923 281.202,13.177 281.202,19.798 279.707,21.293 279.707,182.046 280.5,182.839 280.5,183.807 281.169,184.475 v2(281.169,184.486) 281.202,184.519 281.202,239.978 CN24.48@280.18,241 ; 383.057,183.369 383.057,183.482 383.623,184.049 v1(383.623,184.154) ; 383.057,183.424 384.184,182.296 387.668,182.296 390.327,182.296 CN25.48@391.445,183.415
  FlatSat VCC w0.762: v2(23,222) 24,221 24,214 26,212 26,185.178 v2(26.775,184.402) ; v2(381,184.071) 382.355,184.071 383.057,183.369
  Bottom Layer w0.381: v1(66.477,232.033) 66.477,233.353 65.735,234.095 65.735,242.215 CN23.47@67.06,243.54 ; v1(172.797,232.033) 172.797,233.353 172.055,234.095 172.055,242.215 CN21.47@173.38,243.54 ; v1(279.337,232.033) 279.337,233.353 278.595,234.095 278.595,242.215 CN24.47@279.92,243.54
H1-49: CN21.49 CN21.50 CN22.49 CN22.50 CN23.49 CN23.50 CN24.49 CN24.50 CN25.49 CN25.50 R26.2 U7.7 | length 1114.4
  Top Layer w0.381: v1(383.623,186.623) 384.54,187.54 392.66,187.54 CN25.49@393.985,186.215
  Top Layer w0.762: R26.2@10.016,214 14,214 ; U7.7@10.53,217.365 12.554,217.365 13,216.919 13,215 14,214 ; v2(27,214) 14,214 ; v2(29.183,186.876) v2(62.76,186.876) v2(65.156,186.876) v2(169.08,186.876) v2(171.476,186.876) v2(275.62,186.876) v2(278.016,186.876) 380.711,186.876 v2(381.043,186.545)
  FlatSat VCC w0.381: v2(62.76,186.876) 63.76,187.876 63.76,231.908 v1(63.767,231.915) ; CN23.50@64.52,241 65.639,239.881 65.639,237.223 65.639,234.253 65.156,233.771 v2(65.156,186.876) ; v2(169.08,186.876) 170.08,187.876 170.08,231.908 v1(170.087,231.915) ; CN21.50@170.84,241 171.959,239.881 171.959,237.223 171.959,234.253 171.476,233.771 v2(171.476,186.876) ; v1(276.627,231.915) 276.62,231.908 276.62,187.876 v2(275.62,186.876) 275.62,186.773 275,186.153 275,16.317 275.987,15.33 275.987,13.345 CN22.50@277.408,11.923 ; CN24.50@277.38,241 278.499,239.881 278.499,237.223 278.499,234.253 278.016,233.771 v2(278.016,186.876) 277.4,186.261 277.4,185.968 275.814,184.381 275.814,19.186 276.785,18.215 276.785,16.836 277.408,16.213 CN22.49@277.408,14.463 ; 383.193,185.773 383.289,185.773 383.965,185.096 387.668,185.096 390.327,185.096 CN25.50@391.445,186.215 ; 383.246,186.246 v1(383.623,186.623)
  FlatSat VCC w0.762: v2(27,214) 28,213 28,188.059 v2(29.183,186.876) ; v2(381.043,186.545) 382.421,186.545 382.983,185.983 383.193,185.773
  Bottom Layer w0.381: v1(63.767,231.915) 63.767,233.522 63.195,234.095 63.195,242.215 CN23.49@64.52,243.54 ; v1(170.087,231.915) 170.087,233.522 169.515,234.095 169.515,242.215 CN21.49@170.84,243.54 ; v1(276.627,231.915) 276.627,233.522 276.055,234.095 276.055,242.215 CN24.49@277.38,243.54
H1-51: CN21.51 CN21.52 CN22.51 CN22.52 CN23.51 CN23.52 CN24.51 CN24.52 CN25.51 CN25.52 R28.2 U9.7 | length 1089.3
  Top Layer w0.762: U9.7@13.53,209.365 15.554,209.365 16,208.919 16,207 17,206 ; R28.2@14.016,206 17,206 ; v2(30,206) 17,206 ; v2(31.464,189.559) v2(60.032,189.559) v2(62.54,189.559) v2(166.352,189.559) v2(168.86,189.559) v2(272.892,189.559) v2(275.4,189.559) 380.441,189.559 v2(381,189)
  FlatSat VCC w0.381: v2(60.032,189.559) 61.035,190.562 61.035,234.05 60.735,234.35 60.735,242.555 CN23.51@61.72,243.54 ; CN23.52@61.98,241 63.099,239.881 63.099,234.65 62.418,233.97 62.418,227.11 62.54,226.989 v2(62.54,189.559) ; v2(166.352,189.559) 167.433,190.64 167.433,233.238 167.055,233.617 167.055,242.555 CN21.51@168.04,243.54 ; CN21.52@168.3,241 169.419,239.881 169.419,234.65 168.694,233.925 168.694,227.059 168.86,226.893 v2(168.86,189.559) ; CN24.51@274.58,243.54 273.595,242.555 273.595,233.822 273.959,233.458 273.959,190.626 v2(272.892,189.559) 272,188.667 272,19 273,18 273,14 274.868,12.132 CN22.52@274.868,11.923 ; CN24.52@274.84,241 275.959,239.881 275.959,234.65 275.292,233.983 275.292,227.119 275.4,227.011 v2(275.4,189.559) 275.4,189.456 274.865,188.92 274.865,188.667 274,187.803 274,15.464 274.868,14.595 CN22.51@274.868,14.463 ; 382.966,188.904 384.062,190 393,190 393.985,189.015 CN25.51@393.985,188.755 ; 383.075,188.431 383.119,188.431 383.914,187.636 390.327,187.636 CN25.52@391.445,188.755
  FlatSat VCC w0.762: v2(30,206) 31,205 31,190.023 v2(31.464,189.559) ; v2(381,189) 382.506,189 382.784,188.722 383.075,188.431
H1_N: CN20.1 CN21.1 CN22.1 CN24.1 CN25.1 S3.2A | length 888.3
  Top Layer w0.203: CN20.1@6.38,125.2 5.732,125.848 5.732,125.995 5.613,126.114 3,126.114 2,125.114 2,121 4,119 6,117 12.019,117 12.19,116.828 15.497,116.828 15.669,117 18,117 22,121 49,121 50.711,122.711 72.652,122.711 72.722,122.711 73.179,122.711 73.179,122.584 73.636,122.584 73.636,122.711 73.636,123.789 74.094,123.789 74.094,122.711 74.094,122.584 74.551,122.584 74.551,122.711 74.551,123.789 75.008,123.789 75.008,122.711 75.008,122.584 75.465,122.584 75.465,122.711 75.465,123.789 75.922,123.789 75.922,122.711 75.922,122.584 76.38,122.584 76.38,122.711 76.38,123.789 76.837,123.789 76.837,122.711 76.837,122.584 77.294,122.584 77.294,122.711 77.523,122.711 v1(143.167,122.711) v1(244,122.711) v1(345.503,122.711) v1(356,122.711) 376.295,122.711 382.503,116.503 391.503,116.503 397.385,122.385 397.919,122.919 397.919,125.081 397,126 396.831,126.169 394.753,126.169 394.634,126.05 394.634,125.903 CN25.1@393.985,125.255 ; v1(142.356,193) 142.356,196.431 142.475,196.55 S3.2A@143.27,196.55 ; CN21.1@231.8,243.54 231.152,244.188 231.005,244.188 230.886,244.307 230.886,244.521 231.365,245 237,245 239,243 244,238 v1(244,192) ; CN24.1@338.34,243.54 337.692,244.188 337.545,244.188 337.426,244.307 337.426,244.521 337.905,245 344,245 347,242 356,233 v1(356,192) ; CN22.1@338.368,14.463 337.72,15.112 337.72,17.288 336.11,18.898 336.11,109.11 v1(345,118)
  Bottom Layer w0.203: v1(142.356,193) 142.356,123.523 v1(143.167,122.711) v1@143.25,122.711 ; v1(244,122.711) v1(244,192) ; v1(345,118) 345.586,118.586 345.586,119.343 345.503,119.426 v1(345.503,122.711) ; v1(356,122.711) v1(356,192)
H1_P: CN20.3 CN21.3 CN22.3 CN24.3 CN25.3 S3.1A | length 889.5
  Top Layer w0.203: CN20.3@6.38,127.74 6.132,127.492 6.132,126.986 5.971,126.826 2.705,126.826 1.289,125.409 1.289,120.705 3.749,118.246 5.705,116.289 11.724,116.289 11.896,116.117 15.792,116.117 15.964,116.289 18.295,116.289 22.295,120.289 49.295,120.289 51.006,122 v1(142.873,122) v1(244.711,122) v1(344.792,122) v1(356.711,122) 376,122 382.208,115.792 391.797,115.792 398.096,122.091 398.63,122.624 398.63,125.376 397.125,126.88 394.394,126.88 394.233,127.041 394.233,127.547 CN25.3@393.985,127.795 ; S3.1A@140.73,196.55 141.525,196.55 141.644,196.431 v1(141.644,193) ; CN21.3@229.26,243.54 229.508,243.788 230.014,243.788 230.174,243.949 230.174,244.816 231.07,245.711 237.295,245.711 240.006,243 244.711,238.295 v1(244.711,192) ; CN24.3@335.8,243.54 336.048,243.788 336.554,243.788 336.714,243.949 336.714,244.816 337.61,245.711 344.295,245.711 348.006,242 356.711,233.295 v1(356.711,192) ; CN22.3@335.828,14.463 335.828,14.801 335.399,15.231 335.399,109.404 v1(344.497,118.503)
  Bottom Layer w0.203: v1(141.644,193) 141.644,123.228 v1(142.873,122) v1@142.916,121.957 ; v1(244.711,122) v1(244.711,192) ; v1(344.497,118.503) 344.874,118.88 344.874,119.049 344.792,119.131 v1(344.792,122) ; v1(356.711,122) v1(356.711,192)
H2-1: CN20.53 CN21.53 CN22.53 CN23.53 CN24.53 CN25.53 U16.15 | length 851.8
  Top Layer w0.203: v1(17.192,126.437) 123.209,126.437 123.256,126.484 230.235,126.484 v1(230.248,126.497) ; v1(124.243,232.728) 124.243,237.228 CN23.53@125.48,238.465 ; v1@230.22,126.484 336.09,126.484 v1(336.103,126.471) 336.124,126.492 v1(383.174,126.492) ; v1(230.563,232.728) 230.563,237.228 CN21.53@231.8,238.465 ; U16.15@239.325,114.87 239.325,115.913 239.832,116.421 v1(239.832,116.994) ; v1(337.103,232.728) 337.103,237.228 CN24.53@338.34,238.465
  Bottom Layer w0.203: CN20.53@11.455,125.2 12.692,126.437 v1(17.192,126.437) ; v1(123.243,126.471) 123.277,126.471 124.243,127.437 v1(124.243,232.728) ; v1@230.181,126.505 230.181,127.055 230.563,127.437 v1(230.563,232.728) ; v1(230.248,126.497) 230.295,126.45 230.295,126.375 239.562,117.108 239.637,117.108 239.75,116.994 v1(239.832,116.994) ; v1(336.103,126.471) v1@336.103,126.437 ; v1(337.103,232.728) 337.103,127.437 v1@336.103,126.437 ; CN22.53@338.368,9.388 338.368,10.467 336.858,11.978 336.858,15.196 335.547,16.508 335.547,17.21 335.103,17.653 335.103,36 335.103,125.437 v1@336.103,126.437 ; v1(383.174,126.492) 387.673,126.492 CN25.53@388.91,125.255
H2-3: CN20.55 CN21.55 CN22.55 CN23.55 CN24.55 CN25.55 U16.18 | length 851.1
  Top Layer w0.203: v1(17.185,128.182) v1(121.498,128.182) v1(227.818,128.182) v1(334.358,128.182) 362.403,128.182 362.514,128.293 383.124,128.293 v1(383.18,128.237) ; v1(122.498,232.735) 122.498,234.877 121.89,235.485 121.89,237.41 CN23.55@122.94,238.46 ; v1(228.818,232.937) 228.818,234.877 228.21,235.485 228.21,237.41 CN21.55@229.26,238.46 ; v1(236.797,117.609) 236.797,116.491 237.375,115.913 U16.18@237.375,114.87 ; v1(335.358,232.735) 335.358,234.877 334.75,235.485 334.75,237.41 CN24.55@335.8,238.46
  Bottom Layer w0.203: CN20.55@11.46,127.74 12.51,128.79 14.435,128.79 15.043,128.182 v1(17.185,128.182) ; v1(121.498,128.182) 122.498,129.182 v1(122.498,232.735) ; v1(228.818,232.937) 228.818,129.182 v1(227.818,128.182) 227.364,127.728 227.364,126.636 236.333,117.667 236.739,117.667 v1(236.797,117.609) ; v1(335.358,232.735) 335.358,129.182 v1(334.358,128.182) 333.619,127.443 333.619,18.142 333.381,17.905 333.381,16.566 334,15.947 334,15.514 334.318,15.196 334.318,11.978 335.828,10.467 CN22.55@335.828,9.383 ; v1(383.18,128.237) 385.322,128.237 385.93,128.845 387.855,128.845 CN25.55@388.905,127.795
H2-4: CN20.56 CN21.56 CN22.56 CN23.56 CN24.56 CN25.56 U16.17 | length 837.5
  Top Layer w0.203: CN20.56@14,127.74 14.091,127.649 v1(122.031,127.649) v1(228.351,127.649) v1(334.891,127.649) 383.346,127.649 383.468,127.771 386.341,127.771 CN25.56@386.365,127.795 ; v1(237.518,116.994) 237.518,116.421 238.025,115.913 U16.17@238.025,114.87 ; v1(333.915,17.235) 333.915,17.153 333.687,16.925 333.687,16.839 334.318,16.208 334.318,8.354 CN22.56@335.828,6.843
  Bottom Layer w0.203: v1(122.031,127.649) 123.031,128.649 CN23.56@123.031,235.829 ; CN21.56@229.351,235.829 229.351,128.649 v1(228.351,127.649) 228.064,127.361 228.064,127.096 232.806,122.355 237.518,117.643 v1(237.518,116.994) ; v1(333.915,17.235) 333.973,17.294 333.973,17.551 334,17.578 334,126.757 v1(334.891,127.649) 335.891,128.649 CN24.56@335.891,235.829
H2-5: CN20.57 CN21.57 CN22.57 CN23.57 CN24.57 CN25.57 U15.13 | length 846.5
  Top Layer w0.203: v1(17.192,130.902) 17.274,130.902 17.418,130.759 v1(225.241,130.759) v1(331.781,130.759) 362.403,130.759 362.541,130.896 382.902,130.896 382.927,130.872 383.115,130.872 v1(383.174,130.813) ; v1(119.921,232.728) 119.921,234.845 119.35,235.417 119.35,237.41 CN23.57@120.4,238.46 ; v1(226.241,232.728) 226.241,234.868 225.67,235.439 225.67,237.41 CN21.57@226.72,238.46 ; U15.13@230.625,114.87 230.625,115.913 231.132,116.421 v1(231.132,116.994) ; v1(332.781,232.728) 332.781,234.904 332.21,235.475 332.21,237.41 CN24.57@333.26,238.46
  Bottom Layer w0.203: CN20.57@11.46,130.28 12.51,131.33 14.435,131.33 14.803,130.962 14.833,130.931 14.872,130.902 v1(17.192,130.902) ; v1(118.921,130.759) 119.921,131.759 v1(119.921,232.728) ; v1(226.241,232.728) 226.241,131.759 v1(225.241,130.759) 225.241,125.759 231.132,119.868 v1(231.132,116.994) ; v1(332.781,232.728) 332.781,131.759 v1(331.781,130.759) 330.853,129.83 330.853,16.121 331.778,15.196 331.778,11.978 333.288,10.467 CN22.57@333.288,9.383 ; v1(383.174,130.813) 383.232,130.872 383.421,130.872 383.445,130.896 385.441,130.896 385.93,131.385 387.855,131.385 CN25.57@388.905,130.335
H2-7: CN20.59 CN21.59 CN22.59 CN23.59 CN24.59 CN25.59 U15.17 | length 843.9
  Top Layer w0.203: v1(17.185,133.278) v1(116.402,133.278) v1(222.722,133.278) v1(329.262,133.278) 362.403,133.278 362.526,133.401 382.908,133.401 382.918,133.391 383.122,133.391 v1(383.18,133.333) ; v1(117.402,232.735) 117.402,234.893 116.81,235.485 116.81,237.41 CN23.59@117.86,238.46 ; v1(223.722,232.735) 223.722,234.893 223.13,235.485 223.13,237.41 CN21.59@224.18,238.46 ; v1(227.518,116.994) 227.518,116.421 228.025,115.913 U15.17@228.025,114.87 ; v1(330.262,232.735) 330.262,234.893 329.67,235.485 329.67,237.41 CN24.59@330.72,238.46
  Bottom Layer w0.203: CN20.59@11.46,132.82 12.51,133.87 14.435,133.87 15.027,133.278 v1(17.185,133.278) ; v1(116.402,133.278) 117.402,134.278 v1(117.402,232.735) ; v1(223.722,232.735) 223.722,134.278 v1(222.722,133.278) 222.722,124.278 227.518,119.482 v1(227.518,116.994) ; v1(330.262,232.735) 330.262,134.278 v1(329.262,133.278) 327.927,131.942 327.927,16.508 329.238,15.196 329.238,11.978 330.748,10.467 CN22.59@330.748,9.383 ; v1(383.18,133.333) 385.338,133.333 385.93,133.925 387.855,133.925 CN25.59@388.905,132.875
H2-8: CN20.60 CN21.60 CN22.60 CN23.60 CN24.60 CN25.60 U15.16 | length 830.4
  Top Layer w0.203: CN20.60@14,132.82 14.076,132.744 v1(116.936,132.744) v1(223.256,132.744) v1(329.796,132.744) 383.346,132.744 383.459,132.857 386.348,132.857 CN25.60@386.365,132.875 ; U15.16@228.675,114.87 v1(228.675,117.679) ; v1(328.577,17.235) 328.577,16.869 329.238,16.208 329.238,8.354 CN22.60@330.748,6.843
  Bottom Layer w0.203: v1(116.936,132.744) 117.936,133.744 CN23.60@117.936,235.844 ; CN21.60@224.256,235.844 224.256,133.744 v1(223.256,132.744) 223.256,124.744 228.675,119.325 v1(228.675,117.679) ; v1(328.577,17.235) 328.577,131.526 v1(329.796,132.744) 330.796,133.744 CN24.60@330.796,235.844
H2-9: CN20.61 CN21.61 CN22.61 CN23.61 CN24.61 CN25.61 U14.13 | length 839.7
  Top Layer w0.203: v1(17.185,135.835) 17.261,135.835 17.457,136.031 v1(113.845,136.031) v1(220.165,136.031) v1(326.705,136.031) 362.403,136.031 362.5,135.935 383.059,135.935 383.1,135.894 v1(383.18,135.894) ; v1(114.845,232.735) 114.845,234.91 114.27,235.485 114.27,237.415 CN23.61@115.32,238.465 ; U14.13@220.625,114.87 220.625,115.913 221.132,116.421 v1(221.132,116.994) ; v1(221.165,232.735) 221.165,234.91 220.59,235.485 220.59,237.415 CN21.61@221.64,238.465 ; v1(327.705,232.735) 327.705,234.91 327.13,235.485 327.13,237.415 CN24.61@328.18,238.465
  Bottom Layer w0.203: CN20.61@11.455,135.36 12.505,136.41 14.435,136.41 15.01,135.835 v1(17.185,135.835) ; v1(113.845,136.031) 114.845,137.031 v1(114.845,232.735) ; v1(221.132,116.994) 221.132,118.868 219.725,120.275 219.725,135.508 220.165,135.949 v1(220.165,136.031) 221.165,137.031 v1(221.165,232.735) ; v1(327.705,232.735) 327.705,137.031 v1(326.705,136.031) 325.712,135.039 325.712,16.182 326.698,15.196 326.698,11.978 328.208,10.467 CN22.61@328.208,9.388 ; v1(383.18,135.894) 383.183,135.89 385.355,135.89 385.93,136.465 387.86,136.465 CN25.61@388.91,135.415
H2-10: CN20.62 CN21.62 CN22.62 CN23.62 CN24.62 CN25.62 U14.12 | length 826.6
  Top Layer w0.203: CN20.62@14,135.36 14.058,135.302 17.406,135.302 17.465,135.36 v1(114.378,135.36) v1(220.698,135.36) v1(327.238,135.36) 327.321,135.36 327.467,135.214 383.258,135.214 383.463,135.419 386.361,135.419 CN25.62@386.365,135.415 ; U14.12@221.275,114.87 221.275,115.913 221.782,116.421 v1(221.782,117.679) ; v1(326.246,17.235) 326.246,17.153 326.037,16.944 326.037,16.869 326.698,16.208 326.698,8.354 CN22.62@328.208,6.843
  Bottom Layer w0.203: v1(114.378,135.36) 115.378,136.36 CN23.62@115.378,235.862 ; CN21.62@221.698,235.862 221.698,136.36 v1(220.698,135.36) 220.381,135.043 220.381,120.619 221.782,119.218 v1(221.782,117.679) ; v1(326.246,17.235) 326.264,17.254 326.264,134.386 v1(327.238,135.36) 328.238,136.36 CN24.62@328.238,235.862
